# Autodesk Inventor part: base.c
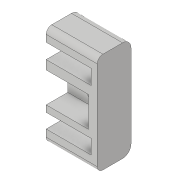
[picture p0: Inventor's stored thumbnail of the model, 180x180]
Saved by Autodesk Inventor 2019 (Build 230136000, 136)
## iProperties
Created: 2020-02
Part Number: base.c
Material: Generic
Document SubType Name: Modeling
Designer: hp
Density: 1 g/cm^3
Appearance: Default
Author: hp
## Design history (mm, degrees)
sketch "Sketch1"
  geometry: L1 (-2.411, 9.141)-(6.68, 9.141); L2 (6.68, 9.141)-(6.68, -8.689); L3 (6.68, -8.689)-(-2.411, -8.689); L4 (-2.411, -8.689)-(-2.411, 9.141); 1 further point
  constraints: 8 end point, 2 parallel, 1 horizontal, 1 perpendicular
extrude "Extrusion1" new body sketch "Sketch1" distance "d0" = 6; taper "d1" = 0 deg
fillet "Fillet1" dims "d2" = 1.5
fillet "Fillet2" dims "d3" = 1
sketch "Sketch2"
  geometry: L1 (6, 15.33)-(6, -0.5) reference; L2 (6, 4.477)-(2.16, 4.477); L3 (2.16, 4.477)-(2.16, 9.851); L4 (2.16, 9.851)-(6, 9.851); 1 further point
  constraints: 6 end point, 3 perpendicular, 2 point on line
extrude "Extrusion2" cut sketch "Sketch2" stored distance "d4" = 15; taper "d5" = 0 deg
sketch "Sketch3"
  geometry: L1 (6, -0.5)-(6, 15.33) reference; L2 (6, 0.76)-(3.315, 0.76); L3 (3.315, 0.76)-(3.315, 3.322); L4 (3.315, 3.322)-(6, 3.322); L5 (6, 14.12)-(3.315, 14.12); L6 (3.315, 14.12)-(3.315, 11.458); L7 (3.315, 11.458)-(6, 11.458); 1 further point
  constraints: 12 end point, 6 point on line, 3 perpendicular, 1 horizontal, 1 parallel
extrude "Extrusion3" cut sketch "Sketch3" distance "d6" = 8; taper "d7" = 0 deg
sketch "Sketch4"
  geometry: L1 (-5.589, 4.269)-(2.411, 4.269) reference; C1 r 2.714 at (-1.205, -4.57); C2 r 2.714 at (-1.205, 4.269); 1 further point
  constraints: 2 centre point, 1 point on line
extrude "Extrusion4" join sketch "Sketch4" distance "d8" = 0.5; taper "d9" = 0 deg
sketch "Sketch5"
  geometry: L1 (-6.68, -7.689)-(2.411, -7.689) reference; L2 (2.411, 8.141)-(-6.68, 8.141) reference; C1 r 0.498 at (1.808, -7.689); C2 r 0.52 at (-6.027, -7.689); C3 r 0.452 at (-6.027, 8.388); C4 r 0.498 at (1.808, 8.141); 1 further point
  constraints: 4 centre point, 2 point on line
extrude "Extrusion5" cut sketch "Sketch5" distance "d10" = 5; taper "d11" = 0 deg
sketch "Sketch6"
  geometry: L1 (2.411, 8.141)-(-6.68, 8.141) reference; L2 (-6.68, 7.641)-(2.411, 7.641) reference; C1 r 0.5 at (-5.726, 8.141); C2 r 0.5 at (1.657, 8.141); 1 further point
  constraints: 2 centre point, 1 point on line, 1 tangent
extrude "Extrusion6" cut sketch "Sketch6" distance "d12" = 5; taper "d13" = 0 deg
sketch "Sketch7"
  geometry: L1 (1.222, -5.784)-(2.361, -5.784); L2 (2.361, -5.784)-(2.361, -3.616); L3 (2.361, -3.616)-(1.222, -3.867); L4 (2.411, -3.867)-(-5.589, -3.867) reference; A1 r 2.714 centre (-1.205, -4.57) between (-0.492, -7.189) and (-1.919, -7.189) reference; 1 further point
  constraints: 6 end point, 1 horizontal, 1 perpendicular, 1 point on circle, 1 point on line
sketch "Sketch8"
  geometry: L1 (-5.726, 7.641)-(1.657, 7.641) reference; L2 (-6.68, -7.689)-(2.411, -7.689) reference; C1 r 0.427 at (-1.607, 7.641); C2 r 0.43 at (-1.607, 0.954); C3 r 0.455 at (-1.607, -1.256); C4 r 0.455 at (-1.152, -7.689); 1 further point
  constraints: 4 centre point, 2 point on line
extrude "Extrusion7" cut sketch "Sketch8" distance "d14" = 5; taper "d15" = 0 deg
body "Solid1"
